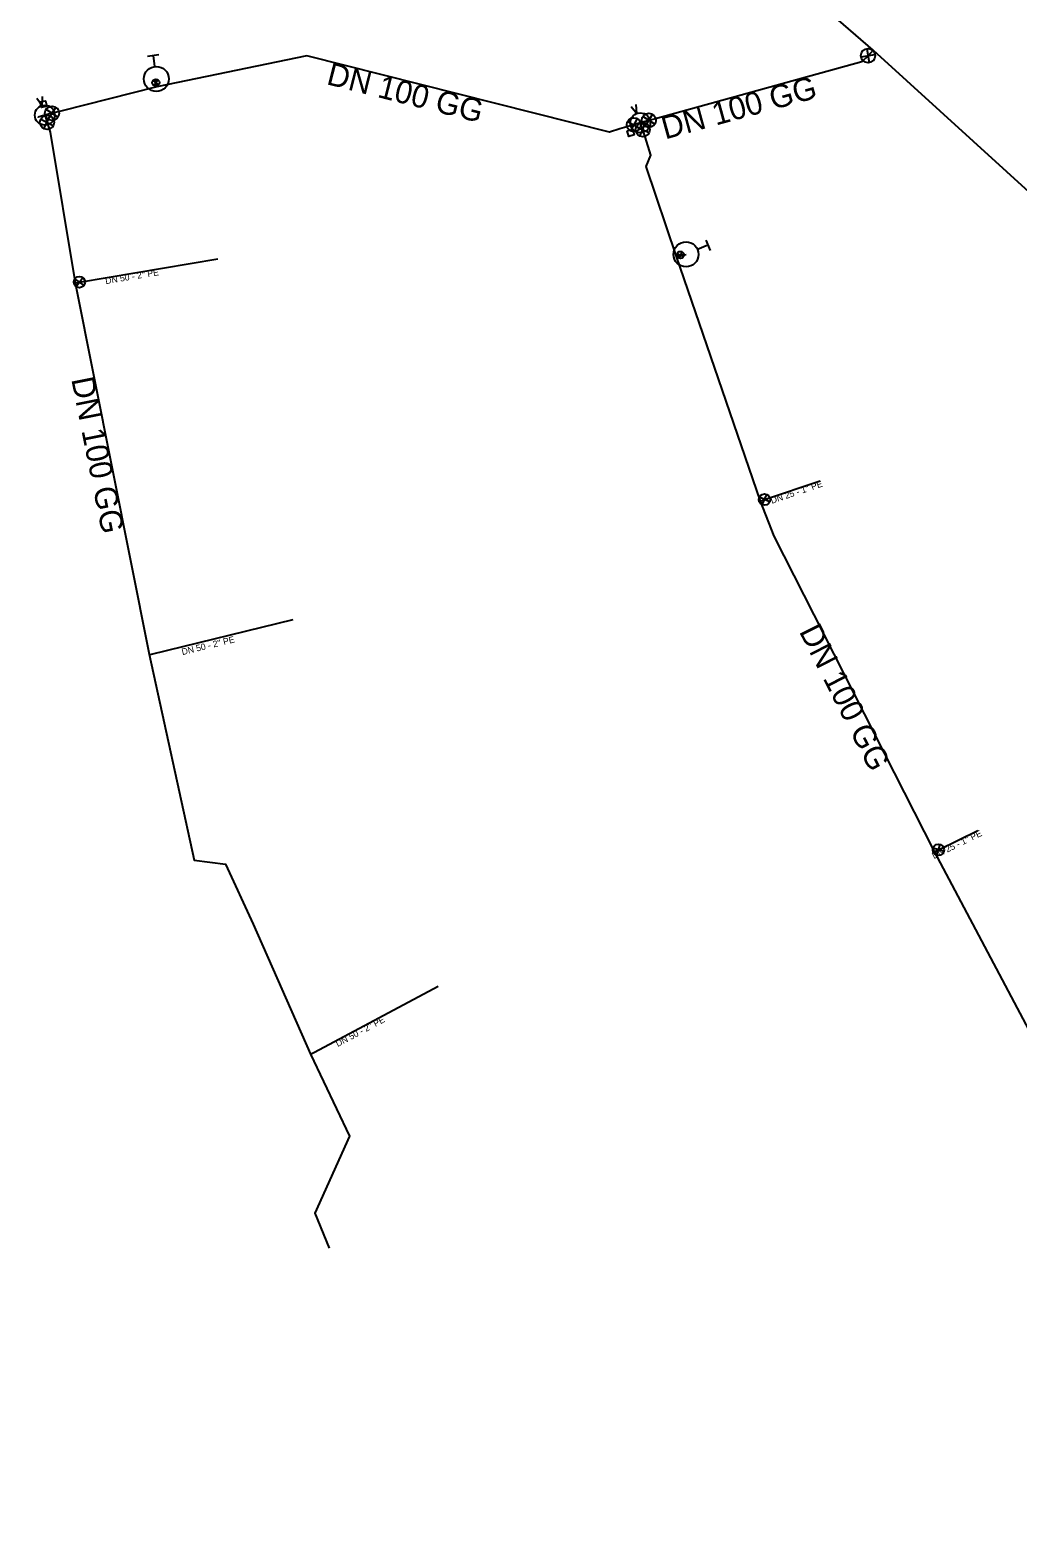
# Model space of a CAD drawing. Extents: x -443519 to -443021, y -1121477 to -1120870.
# Drawn here: x -443519.5 to -443449.9, y -1121056.5 to -1120950.3 of the extents above; entities that cross this region are included whole.
import ezdxf

# ---------------------------------------------------------------- set-up
doc = ezdxf.new("R2010")
doc.units = 0
for name, color, linetype in [('_hydrantova_odbocka_', 7, 'Continuous'), ('_pripojka_priblizne_', 7, 'Continuous'), ('_voda_smvak_prevzato_z_dokumentace_', 7, 'Continuous'), ('Default', 7, 'Continuous'), ('MoLevel 27', 7, 'Continuous'), ('MoLevel 28', 7, 'Continuous'), ('MoLevel 30', 7, 'Continuous'), ('MoLevel 32', 7, 'Continuous'), ('MoLevel 42', 7, 'Continuous'), ('MoLevel 46', 7, 'Continuous'), ('MoLevel 53', 7, 'Continuous')]:
    doc.layers.add(name, color=color, linetype=linetype)

# ---------------------------------------------------------------- blocks, each defined once
blk = doc.blocks.new('_uzaver_')
at = {"layer": 'Default'}
for p, q in [((-0.000035, -0.000035), (0.000035, 0.000035)), ((0.000035, -0.000035), (-0.000035, 0.000035))]:
    blk.add_line(p, q, dxfattribs=at)
for radius in [0.00005, 0.0000025]:
    blk.add_circle((0, 0), radius, dxfattribs=at)
blk = doc.blocks.new('_uzaver_pripojka_')
at = {"layer": 'Default'}
for p, q in [((-0.000035, -0.000035), (0.000035, 0.000035)), ((0.000035, -0.000035), (-0.000035, 0.000035))]:
    blk.add_line(p, q, dxfattribs=at)
for radius in [0.00005, 0.0000025]:
    blk.add_circle((0, 0), radius, dxfattribs=at)
blk = doc.blocks.new('_hydrant_voda_')
at = {"layer": 'Default'}
for p, q in [((-0.0000225, 0.000095), (0.0000225, 0.000095)), ((0, 0.000095), (0, 0.00005))]:
    blk.add_line(p, q, dxfattribs=at)
blk.add_circle((0, 0), 0.00005, dxfattribs=at)
blk = doc.blocks.new('_sachta_voda_')
at = {"layer": 'Default'}
blk.add_lwpolyline([(-0.00001, 0.000065), (0, 0.000035), (0.00001, 0.000065)], dxfattribs=at)
blk.add_circle((0, 0), 0.000035, dxfattribs=at)
blk = doc.blocks.new('_poklop_voda_')
at = {"layer": 'Default'}
blk.add_lwpolyline([(-0.00002, 0.00002), (0.00002, 0.00002), (0.00002, -0.00002), (-0.00002, -0.00002), (-0.00002, 0.00002)], dxfattribs=at)

msp = doc.modelspace()

# ---------------------------------------------------------------- linework, layer by layer
at = {"layer": '_hydrantova_odbocka_'}
for points in [[(-443510.54, -1120954.25), (-443510.61, -1120953.96), (-443510.57, -1120953.7)], [(-443473.93, -1120966.21), (-443473.65, -1120966.1), (-443473.26, -1120966.06)]]:
    msp.add_lwpolyline(points, dxfattribs=at)
at = {"layer": '_pripojka_priblizne_'}
for points in [[(-443516.28, -1120968.07), (-443515.99, -1120968.01), (-443506.24, -1120966.37)], [(-443468.01, -1120983.46), (-443467.73, -1120983.34), (-443463.81, -1120982.01)], [(-443511.06, -1120994.26), (-443510.91, -1120994.23), (-443500.93, -1120991.8)], [(-443455.75, -1121008.15), (-443455.48, -1121008.02), (-443452.71, -1121006.67)], [(-443499.71, -1121022.42), (-443499.44, -1121022.28), (-443490.71, -1121017.62)]]:
    msp.add_lwpolyline(points, dxfattribs=at)
at = {"layer": '_voda_smvak_prevzato_z_dokumentace_'}
for p, q in [((-443460.08, -1120951.67), (-443460.44, -1120952.06)), ((-443510.54, -1120954.25), (-443517.29, -1120955.96)), ((-443517.92, -1120956.12), (-443518.43, -1120956.25)), ((-443518.43, -1120956.25), (-443518.27, -1120956.76)), ((-443517.29, -1120955.96), (-443517.92, -1120956.12)), ((-443475.88, -1120956.62), (-443476.48, -1120956.79)), ((-443475.41, -1120956.5), (-443475.88, -1120956.62)), ((-443518.27, -1120956.76), (-443518.1, -1120957.3)), ((-443476.94, -1120956.93), (-443477.93, -1120957.21)), ((-443476.48, -1120956.79), (-443476.94, -1120956.93)), ((-443476.31, -1120957.28), (-443476.48, -1120956.79)), ((-443476.14, -1120957.77), (-443476.31, -1120957.28))]:
    msp.add_line(p, q, dxfattribs=at)
for points in [[(-443460.08, -1120951.67), (-443463.38, -1120948.81), (-443485.21, -1120927.63), (-443485.37, -1120927.47), (-443486.68, -1120926.19)], [(-443477.93, -1120957.21), (-443478.66, -1120957.44), (-443499.98, -1120952.07), (-443510.54, -1120954.25)], [(-443460.44, -1120952.06), (-443460.88, -1120952.5), (-443475.41, -1120956.5)], [(-443460.08, -1120951.67), (-443438.94, -1120970.9), (-443401.64, -1121029.55), (-443398.02, -1121033.8), (-443385.56, -1121056.5)], [(-443518.43, -1120956.25), (-443518.89, -1120956.39), (-443518.89, -1120956.39)], [(-443518.1, -1120957.3), (-443518.06, -1120957.45), (-443516.28, -1120968.07), (-443511.07, -1120994.23), (-443507.9, -1121008.76), (-443505.71, -1121009.04), (-443503.74, -1121013.25), (-443499.71, -1121022.42), (-443496.97, -1121028.2), (-443499.41, -1121033.63), (-443498.4, -1121036.1)], [(-443473.93, -1120966.21), (-443476.07, -1120959.88), (-443475.74, -1120959.07), (-443476.14, -1120957.77)], [(-443439.66, -1121038.67), (-443447.2, -1121024.27), (-443455.75, -1121008.15), (-443467.06, -1120985.91), (-443468.01, -1120983.46), (-443473.93, -1120966.21)]]:
    msp.add_lwpolyline(points, dxfattribs=at)

# ---------------------------------------------------------------- block references
at = {"layer": 'MoLevel 27'}
for p, xscale, yscale, rotation in [((-443460.44, -1120952.06), 10000, 10000, -126.13568621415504), ((-443510.61, -1120953.96), 4999.999999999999, 4999.999999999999, -81.64878611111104), ((-443517.92, -1120956.12), 10000, 10000, 12.6610162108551), ((-443518.27, -1120956.76), 10000, 10000, -71.9793334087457), ((-443476.94, -1120956.93), 10000, 10000, -164.07514165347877), ((-443476.31, -1120957.28), 10000, 10000, -68.65706403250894), ((-443475.88, -1120956.62), 10000, 10000, 12.127091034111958), ((-443473.65, -1120966.1), 5000, 5000, -161.16513055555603)]:
    msp.add_blockref('_uzaver_', p, dxfattribs=dict(at, xscale=xscale, yscale=yscale, rotation=rotation))
at = {"layer": 'MoLevel 28', "xscale": 17636.68430335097}
for p, yscale, rotation in [((-443510.57, -1120953.7), 17636.684303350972, 7.773030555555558), ((-443473.26, -1120966.06), 17636.68430335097, -67.42587777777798)]:
    msp.add_blockref('_hydrant_voda_', p, dxfattribs=dict(at, yscale=yscale, rotation=rotation))
at = {"layer": 'MoLevel 30', "yscale": 19999.999999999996}
for p, xscale, rotation in [((-443518.43, -1120956.25), 20000, 15.898611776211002), ((-443476.48, -1120956.79), 20000.000000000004, 21.141513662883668)]:
    msp.add_blockref('_sachta_voda_', p, dxfattribs=dict(at, xscale=xscale, rotation=rotation))
at = {"layer": 'MoLevel 42', "xscale": 10000, "yscale": 10000}
for p, rotation in [((-443518.52, -1120955.47), 12.721848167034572), ((-443477.15, -1120957.5), 14.601909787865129)]:
    msp.add_blockref('_poklop_voda_', p, dxfattribs=dict(at, rotation=rotation))
at = {"layer": 'MoLevel 53', "xscale": 8000}
for p, yscale, rotation in [((-443515.99, -1120968.01), 7999.999999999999, 9.190598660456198), ((-443467.73, -1120983.34), 8000, 20.581173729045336), ((-443455.48, -1121008.02), 7999.999999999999, 26.836226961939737)]:
    msp.add_blockref('_uzaver_pripojka_', p, dxfattribs=dict(at, yscale=yscale, rotation=rotation))

# ---------------------------------------------------------------- texts
at = {"layer": 'MoLevel 32'}
for s, rotation, p in [("DN 50 - 2'' PE", 9.569, (-443514.13, -1120968.16)), ("DN 25 - 1'' PE", 18.74, (-443467.21, -1120983.64)), ("DN 50 - 2'' PE", 13.6804, (-443508.73, -1120994.3)), ("DN 25 - 1'' PE", 25.9407, (-443455.8, -1121008.68)), ("DN 50 - 2'' PE", 28.1088, (-443497.79, -1121021.92))]:
    msp.add_text(s, height=0.455, rotation=rotation, dxfattribs=at).set_placement(p)
at = {"layer": 'MoLevel 46'}
for rotation, p in [(345.845, (-443498.65, -1120954.06)), (15.367, (-443474.73, -1120957.97)), (281.2699, (-443516.57, -1120974.85)), (296.9499, (-443465.32, -1120992.63))]:
    msp.add_text('DN 100 GG', height=1.605, rotation=rotation, dxfattribs=at).set_placement(p)

doc.saveas('drawing.dxf')
